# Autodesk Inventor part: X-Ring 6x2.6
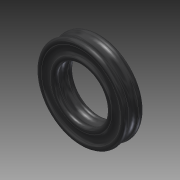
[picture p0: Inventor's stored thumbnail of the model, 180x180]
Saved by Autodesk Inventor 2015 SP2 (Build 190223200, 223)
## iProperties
Created: 2015-08
Part Number: X-Ring 6x2.6
Material: Gummi, Silikon
Document SubType Name: Modeling
Designer: rYan
Mass: 0.175697 g
Surface Area: 2.87106 cm^2
Volume: 0.140558 cm^3
Density: 1.25 g/cm^3
Appearance: Gummi - schwarz - Version 1.1
Author: rYan
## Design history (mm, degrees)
sketch "Skizze1"
  geometry: L1 (-0.91, 5.6)-(0.91, 5.6); L2 (0.91, 5.6)-(0.91, 3.9); L3 (0.91, 3.9)-(-0.91, 3.9); L4 (-0.91, 3.9)-(-0.91, 5.6); L5 (0, 7.834)-(0, -1.306) reference; L6 (-2.651, 0)-(2.651, 0) reference; L7 (0, 5.6)-(0, 3.9); L8 (-0.91, 4.75)-(0.91, 4.75); L9 (-0.91, 5.6)-(-1.31, 5.6); L10 (-0.91, 3.9)-(-1.31, 3.9); L11 (-1.31, 3.9)-(-1.31, 5.6); L12 (-0.91, 5.6)-(-0.91, 6); L13 (-0.91, 3.9)-(-0.91, 3.5); L14 (0.91, 3.9)-(0.91, 3.5); L15 (-0.91, 3.5)-(0.91, 3.5); L16 (0.91, 5.6)-(1.31, 5.6); L17 (0.91, 3.9)-(1.31, 3.9); L18 (-0.91, 6)-(0.91, 6); A1 r 0.4 centre (-0.91, 5.6) between (-0.63, 5.886) and (-1.213, 5.338); A2 r 0.9 centre (0, 6.528) between (-0.63, 5.886) and (0.63, 5.886); A3 r 0.4 centre (0.91, 5.6) between (1.213, 5.338) and (0.63, 5.886); A4 r 0.9 centre (1.894, 4.75) between (1.213, 5.338) and (1.213, 4.162); A5 r 0.4 centre (0.91, 3.9) between (0.63, 3.614) and (1.213, 4.162); A6 r 0.9 centre (0, 2.972) between (0.63, 3.614) and (-0.63, 3.614); A7 r 0.4 centre (-0.91, 3.9) between (-1.213, 4.162) and (-0.63, 3.614); A8 r 0.9 centre (-1.894, 4.75) between (-1.213, 4.162) and (-1.213, 5.338); 1 further point
  constraints: 32 end point, 25 point on circle, 10 tangent, 8 centre point, 7 parallel, 4 horizontal, 4 midpoint, 2 equal radius, 2 vertical, 1 point on line, 3 other
  dimensions: "d0" = 2.5 distance of L13.end L12.end; "d1" = 7 diameter of L15 L6; "d2" = 2.62 distance of L9.end L16.end; "d3" = 0.9 radius of A8; "d4" = 0.4 radius of A1
revolve "Umdrehung1" sketch "Skizze1" stored, may be unused: angle "d5" = 90 deg
node "Volumenkörper1"
